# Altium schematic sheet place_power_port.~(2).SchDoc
size A4
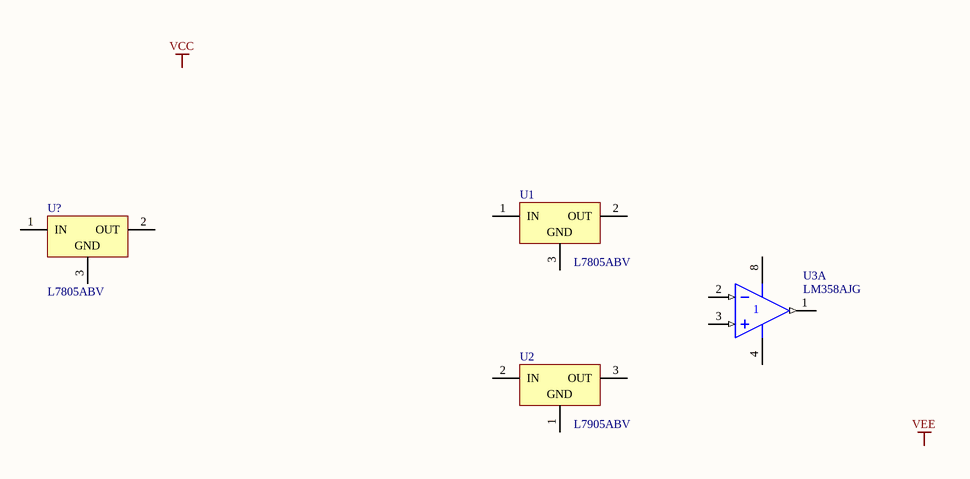
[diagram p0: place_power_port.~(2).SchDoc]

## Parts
U1  L7805ABV  [TO220ABN]
U2  L7905ABV  [TO220V]
U3  LM358AJG  [JG008]  (part A of 2)
U?  L7805ABV  [TO220ABN]

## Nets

Not connected (* = marked no-connect by the designer): U1 1(IN) 2(OUT) 3(GND); U2 1(GND) 2(IN) 3(OUT); U3 1(OUT) 2(IN-) 3(IN+) 4(V-) 8(V+); U? 1(IN) 2(OUT) 3(GND)

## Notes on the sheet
- Labels drawn without touching a wire or pin: VCC, VEE

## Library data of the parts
U1 U? = L7805ABV: Precision 1A Regulator; Note: Tab is connected to pin 3 (GND).
U2 = L7905ABV: ?2%Negative Voltage Regulator; Note: Tab is connected to pin 3 (IN).
U3 = LM358AJG: Dual Operational Amplifier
